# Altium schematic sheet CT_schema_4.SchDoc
size 289 x 230 mm
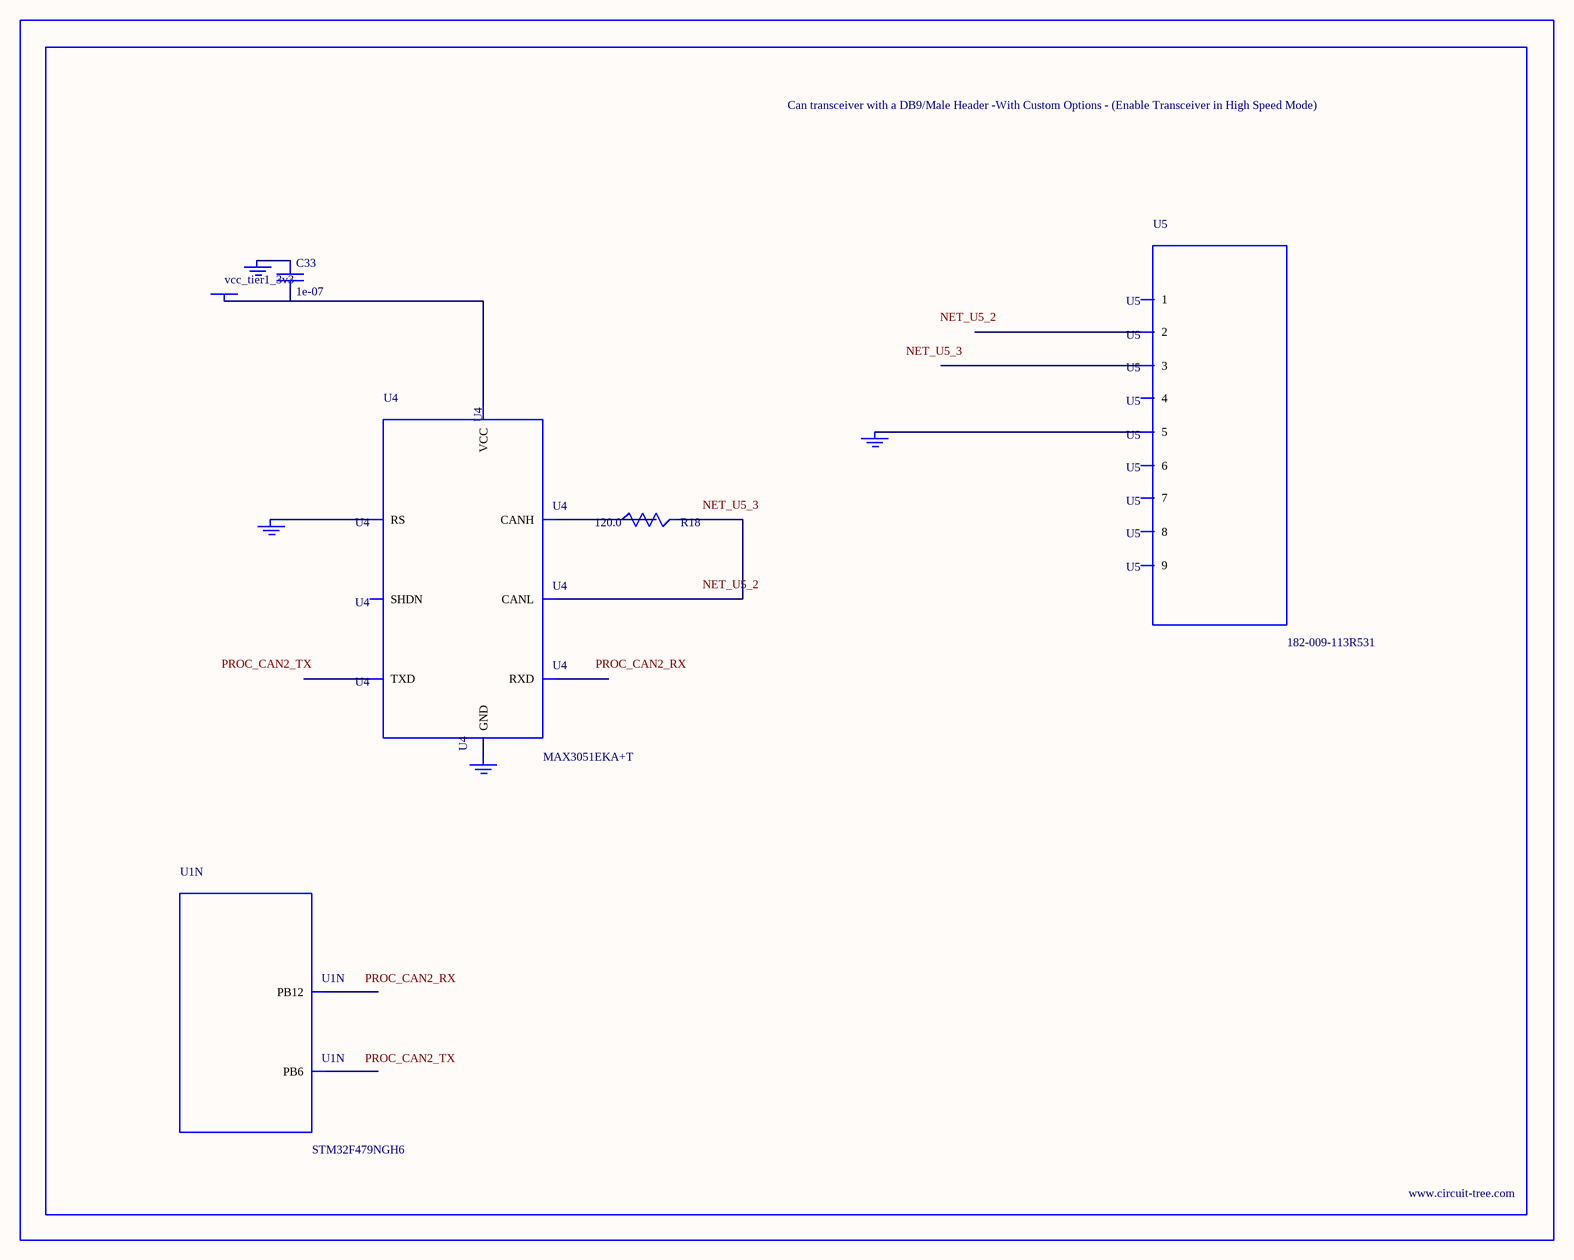
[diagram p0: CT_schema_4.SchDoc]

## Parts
BORDER3  (no value)
C33  1e-07  [C0402]
GND_INSTANCE_3_0  (no value)
GND_INSTANCE_3_1  (no value)
GND_INSTANCE_3_2  (no value)
GND_INSTANCE_3_3  (no value)
POWER_INSTANCE_3_0  vcc_tier1_3v3
R18  120.0  [R0603]
U1  STM32F479NGH6  [TFBGA216]  (part N of 15)
U4  MAX3051EKA+T  [SOT-23-8]
U5  182-009-113R531  [182-009-MALE]

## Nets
NetC33_1: C33.1 GND_INSTANCE_3_0.0(GND)
NetC33_2: C33.2 POWER_INSTANCE_3_0.0(PWR) U4.3(VCC)
NetGND_INSTANCE_3_1_0: GND_INSTANCE_3_1.0(GND) U4.8(RS)
NetGND_INSTANCE_3_2_0: GND_INSTANCE_3_2.0(GND) U4.2(GND)
NetGND_INSTANCE_3_3_0: GND_INSTANCE_3_3.0(GND) U5.5
NetR18_1: R18.1 U4.7(CANH)
NetR18_2: R18.2 U4.6(CANL)

Not connected (* = marked no-connect by the designer): U1 B6(PB6) L13(PB12); U4 1(TXD) 4(RXD) 5(SHDN); U5 1 2 3 4 6 7 8 9

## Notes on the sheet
- Labels drawn without touching a wire or pin: NET_U5_2, NET_U5_3, PROC_CAN2_RX, PROC_CAN2_TX

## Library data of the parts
BORDER3 = BORDER_PAGE3
C33 = C0402C104K3RACTU
GND_INSTANCE_3_0-GND_INSTANCE_3_3 = GND
POWER_INSTANCE_3_0 = PWR
R18 = RC0603JR-07120RL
